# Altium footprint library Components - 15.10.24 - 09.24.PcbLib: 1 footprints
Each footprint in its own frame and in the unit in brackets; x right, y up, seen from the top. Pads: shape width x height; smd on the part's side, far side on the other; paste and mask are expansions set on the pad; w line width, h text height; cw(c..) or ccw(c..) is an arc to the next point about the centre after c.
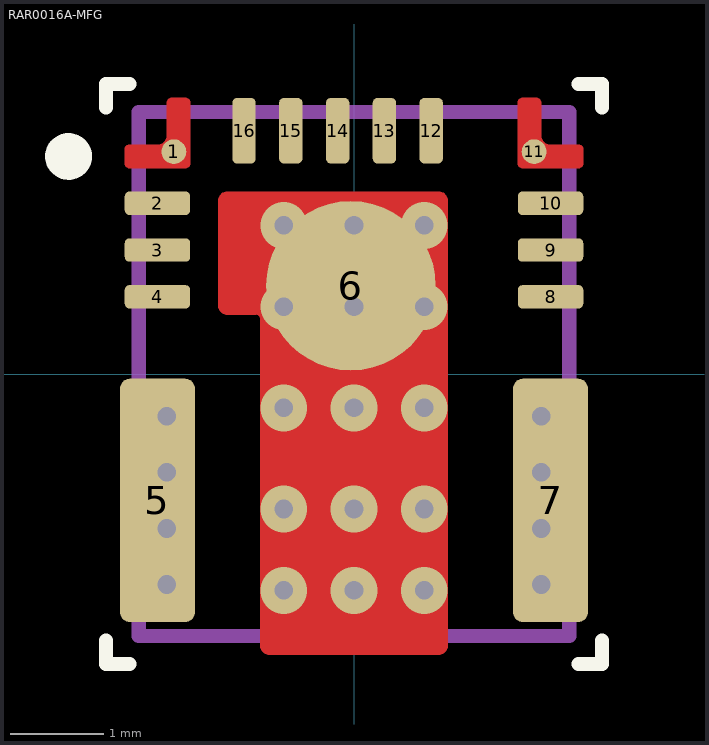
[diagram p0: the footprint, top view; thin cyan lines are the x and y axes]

## RAR0016A-MFG [mm]
pads (16):
  round 0.265 smd paste+0 mask-1000: 1(-1.925,2.375) 11(1.925,2.375)
  rrect40% 0.7x0.25 smd paste+0 mask-1000: 2(-2.1,1.825) 3(-2.1,1.325) 4(-2.1,0.825) 8(2.1,0.825) 9(2.1,1.325) 10(2.1,1.825)
  rrect25% 0.8x2.6 smd paste-1000 mask-1000: 5(-2.1,-1.35) 7(2.1,-1.35)
  round 1.813 smd paste-1000 mask-1000: 6(-0.034,0.943)
  rrect40% 0.25x0.7 smd paste+0 mask-1000: 12(0.825,2.6) 13(0.325,2.6) 14(-0.175,2.6) 15(-0.675,2.6) 16(-1.175,2.6)
via -2,-2.25 diameter 0.5 hole 0.2
via -2,-1.65 diameter 0.5 hole 0.2
via -2,-1.05 diameter 0.5 hole 0.2
via -2,-0.45 diameter 0.5 hole 0.2
via 2,-2.25 diameter 0.5 hole 0.2
via 2,-1.65 diameter 0.5 hole 0.2
via 2,-1.05 diameter 0.5 hole 0.2
via 2,-0.45 diameter 0.5 hole 0.2
via 0.75,-2.312 diameter 0.5 hole 0.2
via 0.75,-1.442 diameter 0.5 hole 0.2
via 0.75,-0.362 diameter 0.5 hole 0.2
via 0.75,0.718 diameter 0.5 hole 0.2
via 0.75,1.588 diameter 0.5 hole 0.2
via 0,1.588 diameter 0.5 hole 0.2
via 0,0.718 diameter 0.5 hole 0.2
via 0,-0.362 diameter 0.5 hole 0.2
via 0,-1.442 diameter 0.5 hole 0.2
via 0,-2.312 diameter 0.5 hole 0.2
via -0.75,1.588 diameter 0.5 hole 0.2
via -0.75,0.718 diameter 0.5 hole 0.2
via -0.75,-0.362 diameter 0.5 hole 0.2
via -0.75,-1.442 diameter 0.5 hole 0.2
via -0.75,-2.312 diameter 0.5 hole 0.2
Top Layer:
  region: -2.4,2.2 -2.41,2.2 -2.428,2.208 -2.442,2.222 -2.45,2.24 -2.45,2.25 -2.45,2.4 -2.45,2.41 -2.442,2.428 -2.428,2.442 -2.41,2.45 -2.4,2.45 -2.1,2.45 -2.08,2.452 -2.044,2.467 -2.017,2.494 -2.002,2.53 -2,2.55 -2,2.9 -2,2.91 -1.992,2.928 -1.978,2.942 -1.96,2.95 -1.95,2.95 -1.8,2.95 -1.79,2.95 -1.772,2.942 -1.758,2.928 -1.75,2.91 -1.75,2.9 -1.75,2.25 -1.75,2.24 -1.758,2.222 -1.772,2.208 -1.79,2.2 -1.8,2.2
  region: 2.4,2.2 2.41,2.2 2.428,2.208 2.442,2.222 2.45,2.24 2.45,2.25 2.45,2.4 2.45,2.41 2.442,2.428 2.428,2.442 2.41,2.45 2.4,2.45 2.1,2.45 2.08,2.452 2.044,2.467 2.017,2.494 2.002,2.53 2,2.55 2,2.9 2,2.91 1.992,2.928 1.978,2.942 1.96,2.95 1.95,2.95 1.8,2.95 1.79,2.95 1.772,2.942 1.758,2.928 1.75,2.91 1.75,2.9 1.75,2.25 1.75,2.24 1.758,2.222 1.772,2.208 1.79,2.2 1.8,2.2
  region: -1.45,1.85 -1.45,1.87 -1.435,1.907 -1.407,1.935 -1.37,1.95 -1.35,1.95 0.9,1.95 0.92,1.95 0.957,1.935 0.985,1.907 1,1.87 1,1.85 1,-2.9 1,-2.92 0.985,-2.957 0.957,-2.985 0.92,-3 0.9,-3 -0.9,-3 -0.92,-3 -0.957,-2.985 -0.985,-2.957 -1,-2.92 -1,-2.9 -1,0.585 -1.001,0.595 -1.008,0.613 -1.022,0.627 -1.04,0.634 -1.05,0.635 -1.35,0.635 -1.37,0.635 -1.407,0.65 -1.435,0.678 -1.45,0.715 -1.45,0.735
Top Overlay:
  circle w0.25: c-3.05,2.325 r0.125
  lines w0.15: -2.65,-2.85 -2.65,-3.1 -2.4,-3.1 ; -2.65,2.85 -2.65,3.1 -2.4,3.1 ; 2.4,-3.1 2.65,-3.1 2.65,-2.85 ; 2.4,3.1 2.65,3.1 2.65,2.85
Top Paste:
  drawing of 8 lines, arcs and shapes, not listed
Top Solder:
  drawing of 16 lines, arcs and shapes, not listed
Mechanical 5:
  lines w0.15: -2.3,-2.8 2.3,-2.8 2.3,2.8 -2.3,2.8 -2.3,-2.8
  text ".Designator" at 0.05,0.192 h0.5
3D body "IC_LMG2100R044_VQFN-FCRLF16.STEP": height 0.25, standoff 0, extent -2.6,-3.1 2.6,3.05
